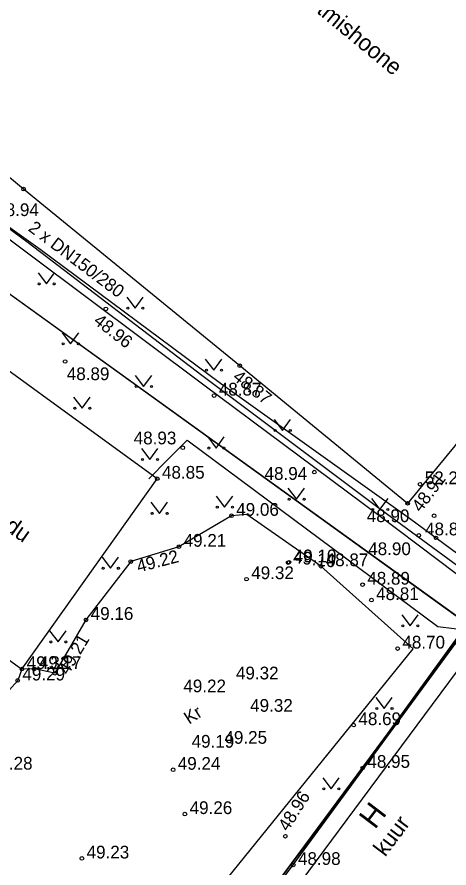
# Model space of a CAD drawing. Extents: x 640876 to 641418, y 6455595 to 6456085.
# Drawn here: x 641167.04 to 641190.78, y 6455847.21 to 6455893.98 of the extents above; entities that cross this region are included whole.
import ezdxf

# ---------------------------------------------------------------- set-up
doc = ezdxf.new("R2010")
doc.units = 0
for name, color, linetype in [('AED', 7, 'Continuous'), ('HALJASTUS', 7, 'Continuous'), ('HOONE', 7, 'Continuous'), ('KORGUS', 7, 'Continuous'), ('MOOTKORG', 7, 'Continuous'), ('MOOTMPUNKT', 7, 'Continuous'), ('MOOTPIIR', 7, 'Continuous'), ('PIIR', 7, 'Continuous'), ('SITRASS', 7, 'Continuous'), ('TEE', 7, 'Continuous'), ('TTRASS', 7, 'Continuous')]:
    doc.layers.add(name, color=color, linetype=linetype)

msp = doc.modelspace()

# ---------------------------------------------------------------- linework, layer by layer
at = {"layer": 'AED'}
msp.add_lwpolyline([(641190.933, 6455807.239), (641184.916, 6455813.051), (641177.832, 6455819.82), (641173.204, 6455824.372), (641168.374, 6455829.07), (641172.424, 6455834.304), (641178.267, 6455842.112), (641182.222, 6455847.378), (641186.037, 6455852.714), (641191.816, 6455860.659), (641196.772, 6455856.219)], dxfattribs=at)
at = {"layer": 'HALJASTUS'}
for p, q in [((641168.194, 6455879.914), (641168.657, 6455879.307)), ((641168.657, 6455879.307), (641169.103, 6455879.914)), ((641173.068, 6455878.587), (641173.532, 6455877.98)), ((641173.532, 6455877.98), (641173.977, 6455878.587)), ((641169.52, 6455876.629), (641169.984, 6455876.023)), ((641169.984, 6455876.023), (641170.429, 6455876.629)), ((641177.387, 6455875.178), (641177.851, 6455874.571)), ((641177.851, 6455874.571), (641178.296, 6455875.178)), ((641173.533, 6455874.274), (641173.996, 6455873.667)), ((641173.996, 6455873.667), (641174.442, 6455874.274)), ((641170.15, 6455873.079), (641170.614, 6455872.472)), ((641170.614, 6455872.472), (641171.059, 6455873.079)), ((641181.168, 6455871.86), (641181.631, 6455871.253)), ((641181.631, 6455871.253), (641182.077, 6455871.86)), ((641177.52, 6455870.898), (641177.984, 6455870.291)), ((641177.984, 6455870.291), (641178.429, 6455870.898)), ((641173.872, 6455870.267), (641174.336, 6455869.66)), ((641174.336, 6455869.66), (641174.781, 6455870.267)), ((641181.931, 6455868.077), (641182.394, 6455867.471)), ((641182.394, 6455867.471), (641182.84, 6455868.077)), ((641177.984, 6455867.646), (641178.448, 6455867.039)), ((641178.448, 6455867.039), (641178.893, 6455867.646)), ((641186.523, 6455867.513), (641186.987, 6455866.907)), ((641186.987, 6455866.907), (641187.432, 6455867.513)), ((641174.403, 6455867.306), (641174.866, 6455866.699)), ((641174.866, 6455866.699), (641175.312, 6455867.306)), ((641171.717, 6455864.287), (641172.18, 6455863.68)), ((641172.18, 6455863.68), (641172.626, 6455864.287)), ((641188.183, 6455861.126), (641188.647, 6455860.52)), ((641188.647, 6455860.52), (641189.092, 6455861.126)), ((641168.832, 6455860.239), (641169.295, 6455859.632)), ((641169.295, 6455859.632), (641169.741, 6455860.239)), ((641186.757, 6455856.581), (641187.221, 6455855.974)), ((641187.221, 6455855.974), (641187.666, 6455856.581)), ((641183.839, 6455852.168), (641184.303, 6455851.561)), ((641184.303, 6455851.561), (641184.748, 6455852.168))]:
    msp.add_line(p, q, dxfattribs=at)
for centre in [(641168.256, 6455879.307), (641169.085, 6455879.307), (641173.131, 6455877.98), (641173.959, 6455877.98), (641169.582, 6455876.023), (641170.411, 6455876.023), (641177.45, 6455874.571), (641178.279, 6455874.571), (641173.595, 6455873.667), (641174.424, 6455873.667), (641170.213, 6455872.472), (641171.041, 6455872.472), (641181.23, 6455871.253), (641182.059, 6455871.253), (641177.583, 6455870.291), (641178.411, 6455870.291), (641173.935, 6455869.66), (641174.764, 6455869.66), (641181.993, 6455867.471), (641182.822, 6455867.471), (641178.047, 6455867.039), (641178.876, 6455867.039), (641186.586, 6455866.907), (641187.414, 6455866.907), (641174.465, 6455866.699), (641175.294, 6455866.699), (641171.779, 6455863.68), (641172.608, 6455863.68), (641188.246, 6455860.52), (641189.075, 6455860.52), (641168.894, 6455859.632), (641169.723, 6455859.632), (641186.82, 6455855.974), (641187.649, 6455855.974), (641183.902, 6455851.561), (641184.73, 6455851.561)]:
    msp.add_circle(centre, 0.055, dxfattribs=at)
at = {"layer": 'HOONE'}
for points in [[(641149.742, 6455963.717), (641189.36, 6455931.349), (641178.797, 6455918.488), (641209.743, 6455893.117), (641188.509, 6455867.25), (641179.281, 6455874.809), (641167.4, 6455884.521), (641162.961, 6455888.191)], [(641154.452, 6455867.469), (641167.313, 6455858.143), (641174.747, 6455868.605), (641161.886, 6455877.931), (641154.452, 6455867.469)], [(641179.081, 6455843.151), (641182.222, 6455847.378), (641191.132, 6455859.552), (641195.718, 6455856.166), (641194.92, 6455855.074)], [(641179.081, 6455843.151), (641182.222, 6455847.378), (641191.132, 6455859.552), (641195.718, 6455856.166), (641194.92, 6455855.074)]]:
    msp.add_lwpolyline(points, dxfattribs=at)
at = {"layer": 'KORGUS'}
for centre in [(641167.4, 6455884.521), (641171.925, 6455877.938), (641169.681, 6455875.046), (641179.281, 6455874.809), (641176.148, 6455870.302), (641183.38, 6455868.965), (641174.747, 6455868.605), (641188.509, 6455867.25), (641189.964, 6455866.57), (641189.118, 6455865.491), (641190.065, 6455865.355), (641173.289, 6455864.053), (641181.934, 6455863.996), (641169.121, 6455857.908), (641181.788, 6455848.955), (641170.604, 6455847.733)]:
    msp.add_circle(centre, 0.1, dxfattribs=at)
at = {"layer": 'MOOTMPUNKT'}
for centre in [(641177.87, 6455873.175), (641189.189, 6455868.302), (641178.828, 6455866.565), (641175.938, 6455864.866), (641181.99, 6455864.01), (641183.745, 6455863.795), (641179.653, 6455863.083), (641186.031, 6455862.781), (641186.517, 6455861.933), (641170.83, 6455860.846), (641187.959, 6455859.27), (641167.313, 6455858.143), (641167.979, 6455858.151), (641167.075, 6455857.516), (641185.544, 6455855.062), (641186.037, 6455852.714), (641175.615, 6455852.608), (641176.267, 6455850.174), (641182.222, 6455847.378)]:
    msp.add_circle(centre, 0.1, dxfattribs=at)
at = {"layer": 'MOOTPIIR'}
msp.add_lwpolyline([(641060.916, 6455895.936), (641100.061, 6455950.482), (641099.586, 6455952.159), (641069.132, 6455984.035), (641066.132, 6455988.623), (641076.463, 6456005.049), (641230.642, 6456010.048), (641237.36, 6455995.24), (641237.24, 6455992.81), (641236.258, 6455990.888), (641229.041, 6455971.315), (641203.026, 6455909.57), (641225.257, 6455906.847), (641239.512, 6455898.491), (641200.195, 6455851.697), (641192.016, 6455859.099), (641169.785, 6455829.138), (641192.025, 6455807.568), (641252.96, 6455758.075), (641231.388, 6455736.74), (641191.474, 6455775.975), (641152.419, 6455787.914), (641136.351, 6455788.307), (641049.066, 6455856.043)], dxfattribs=at)
at = {"layer": 'PIIR'}
for points in [[(641222.58, 6455998.61), (641237.36, 6455995.24), (641235.34, 6455991.29), (641228.11, 6455971.68), (641220.5, 6455953.19), (641213.41, 6455936.25), (641201.58, 6455908.74), (641224.93, 6455905.88), (641191.87, 6455860.58), (641157.02, 6455885.66), (641160.91, 6455891.99), (641102.26, 6455951.82), (641074.95, 6455979.64), (641084.84, 6455991.92)], [(641216.67, 6455752.61), (641192, 6455776.86), (641152.58, 6455788.91), (641136.9, 6455789.33), (641119.28, 6455802.72), (641101.72, 6455816.27), (641098.61, 6455818.83), (641124.03, 6455849.78), (641139.51, 6455868.99), (641157, 6455885.69), (641191.84, 6455860.59), (641168.46, 6455829.03), (641191.37, 6455806.79), (641234.69, 6455771.62)], [(641184.3, 6455828.79), (641199.12, 6455815.36), (641191.36, 6455806.82), (641168.47, 6455829), (641191.87, 6455860.58), (641203.18, 6455849.61)]]:
    msp.add_lwpolyline(points, close=True, dxfattribs=at)
at = {"layer": 'SITRASS'}
for points in [[(641160.717, 6455890.02), (641160.061, 6455889.202), (641160.124, 6455887.433), (641162.714, 6455885.215), (641168.31, 6455881.226), (641178.228, 6455873.851), (641188.611, 6455866.439), (641195.817, 6455861.122), (641198.143, 6455862.18), (641205.423, 6455869.555), (641212.959, 6455877.434), (641219.89, 6455884.166), (641222.806, 6455887.129), (641228.363, 6455892.82), (641230.103, 6455894.633)], [(641174.28, 6455868.6), (641175.337, 6455869.665), (641176.394, 6455870.73), (641176.446, 6455870.679), (641190.159, 6455860.476), (641192.86, 6455860.157), (641202.953, 6455874.327), (641207.15, 6455874.999), (641212.959, 6455877.434)]]:
    msp.add_lwpolyline(points, dxfattribs=at)
at = {"layer": 'TEE'}
for points in [[(641167.313, 6455858.143), (641167.075, 6455857.516), (641164.563, 6455854.713), (641160.999, 6455852.383), (641157.935, 6455852.048), (641154.287, 6455852.849), (641151.802, 6455856.608), (641151.191, 6455860.249), (641150.951, 6455862.79), (641150.519, 6455865.7), (641151.382, 6455869.04), (641153.052, 6455870.892), (641154.71, 6455871.606), (641156.465, 6455871.367), (641156.968, 6455871.01)], [(641175.489, 6455842.795), (641188.807, 6455859.256), (641183.745, 6455863.795), (641179.662, 6455866.63), (641178.828, 6455866.565), (641175.938, 6455864.866), (641173.289, 6455864.053), (641170.83, 6455860.846), (641169.121, 6455857.908), (641167.979, 6455858.151), (641167.313, 6455858.143)]]:
    msp.add_lwpolyline(points, dxfattribs=at)
at = {"layer": 'TTRASS'}
for points in [[(641146.983, 6455877.597), (641147.637, 6455878.312), (641148.076, 6455878.791), (641148.587, 6455879.349), (641156.827, 6455888.351), (641157.502, 6455889.088), (641158.299, 6455888.492), (641167.659, 6455881.582), (641177.2, 6455874.303), (641186.795, 6455867.097), (641195.745, 6455860.541), (641196.509, 6455859.853), (641197.119, 6455860.535), (641205.5, 6455869.137), (641213.939, 6455877.707), (641222.42, 6455886.169), (641230.878, 6455894.702), (641235.947, 6455899.687), (641236.146, 6455899.925), (641236.328, 6455899.987), (641239.542, 6455899.756)], [(641240.141, 6455899.285), (641236.489, 6455899.529), (641236.348, 6455899.464), (641230.948, 6455894.114), (641222.434, 6455885.667), (641213.976, 6455877.157), (641205.539, 6455868.624), (641197.23, 6455859.957), (641196.541, 6455859.328), (641186.928, 6455866.582), (641177.306, 6455873.752), (641167.696, 6455880.94), (641158.359, 6455887.923), (641157.562, 6455888.52), (641156.887, 6455887.782), (641148.647, 6455878.781), (641148.136, 6455878.223), (641147.697, 6455877.743), (641147.022, 6455877.006)]]:
    msp.add_lwpolyline(points, dxfattribs=at)

# ---------------------------------------------------------------- texts
at = {"layer": 'HOONE'}
for s, height, rotation, p in [('Enics AS tootmishoone', 0.9, 320.4148, (641178.145, 6455898.642)), ('puisteliiva ladu', 0.9, 324.9053, (641160.939, 6455869.595)), ('H', 1.2, 52.7844, (641186.71, 6455849.289)), ('kuur', 0.9, 53.0825, (641187.274, 6455847.785))]:
    msp.add_text(s, height=height, rotation=rotation, dxfattribs=at).set_placement(p)
at = {"layer": 'KORGUS'}
for s, p in [(' 48.94', (641165.637, 6455883.038)), (' 48.89', (641169.515, 6455874.021)), (' 48.93', (641173.192, 6455870.492)), (' 48.85', (641174.747, 6455868.605)), (' 48.94', (641180.386, 6455868.541)), ('48.80', (641189.468, 6455865.491)), (' 49.28', (641165.291, 6455852.616)), (' 49.23', (641170.604, 6455847.733))]:
    msp.add_text(s, height=0.7, dxfattribs=at).set_placement(p)
for s, rotation, p in [(' 48.96', 321.7978, (641170.991, 6455877.339)), (' 48.87', 321.3458, (641178.642, 6455874.256)), (' 48.91', 52.9965, (641189.077, 6455866.511)), (' 49.22', 14.6399, (641173.466, 6455863.376)), (' 49.10', 353.9154, (641181.934, 6455863.996)), (' 49.21', 59.3756, (641169.723, 6455857.551)), (' 48.96', 57.5922, (641181.788, 6455848.955))]:
    msp.add_text(s, height=0.7, rotation=rotation, dxfattribs=at).set_placement(p)
at = {"layer": 'MOOTKORG'}
for s, p in [(' 48.87', (641177.87, 6455873.175)), (' 52.20', (641189.189, 6455868.302)), (' 49.06', (641178.828, 6455866.565)), (' 48.90', (641186.003, 6455866.219)), (' 49.21', (641175.938, 6455864.866)), (' 48.90', (641186.083, 6455864.405)), (' 49.10', (641181.99, 6455864.01)), (' 48.87', (641183.745, 6455863.795)), (' 49.32', (641179.653, 6455863.083)), (' 48.89', (641186.031, 6455862.781)), (' 48.81', (641186.517, 6455861.933)), (' 49.16', (641170.83, 6455860.846)), (' 48.70', (641187.959, 6455859.27)), (' 49.32', (641167.313, 6455858.143)), (' 49.17', (641167.979, 6455858.151)), (' 49.29', (641167.075, 6455857.516)), (' 49.32', (641178.812, 6455857.575)), (' 49.22', (641175.922, 6455856.864)), (' 49.32', (641179.593, 6455855.796)), (' 48.69', (641185.544, 6455855.062)), (' 49.25', (641178.18, 6455854.037)), (' 49.19', (641176.375, 6455853.82)), (' 49.24', (641175.615, 6455852.608)), (' 48.95', (641186.037, 6455852.714)), (' 49.26', (641176.267, 6455850.174)), (' 48.98', (641182.222, 6455847.378))]:
    msp.add_text(s, height=0.7, dxfattribs=at).set_placement(p)
at = {"layer": 'TEE'}
msp.add_text('Kr', height=0.7, rotation=32.6696, dxfattribs=at).set_placement((641176.495, 6455855.083))
at = {"layer": 'TTRASS'}
msp.add_text('2 x DN150/280', height=0.7, rotation=322.997, dxfattribs=at).set_placement((641167.607, 6455882.271))

doc.saveas('drawing.dxf')
